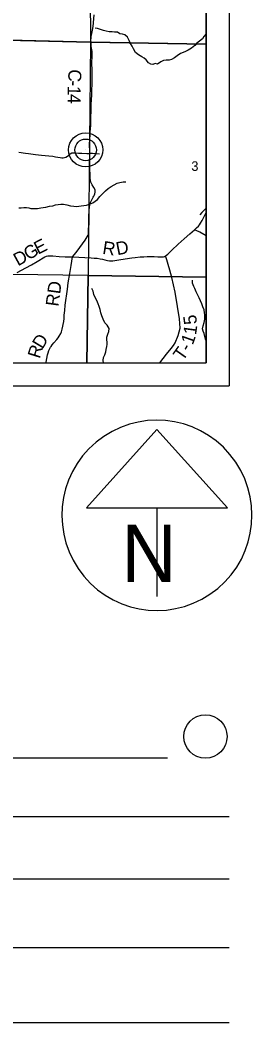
# Model space of a CAD drawing. Extents: x 0 to 34, y 0 to 22.
# Drawn here: x 8.087 to 9.099, y 11.222 to 15.595 of the extents above; entities that cross this region are included whole.
import ezdxf

# ---------------------------------------------------------------- set-up
doc = ezdxf.new("R2010")
doc.units = 0
for name, color, linetype in [('GM_X_Corporation', 7, 'Continuous'), ('GM_X_County_Road', 7, 'Continuous'), ('GM_X_County_Road_Text', 7, 'Continuous'), ('GM_X_Minor_River', 7, 'Continuous'), ('GM_X_Section_Text', 7, 'Continuous'), ('GM_X_Township_Road', 7, 'Continuous'), ('GM_X_Township_Road_Text', 7, 'Continuous'), ('GM_X_Unincorporated', 7, 'Continuous'), ('GM_X_Unincorporated_Location', 7, 'Continuous'), ('SH_Data', 7, 'Continuous'), ('TX_P_1', 7, 'Continuous')]:
    doc.layers.add(name, color=color, linetype=linetype)

msp = doc.modelspace()

# ---------------------------------------------------------------- linework, layer by layer
at = {"layer": 'GM_X_Corporation'}
for points in [[(2.1, 14.1), (8.9, 14.1), (8.9, 19.5152), (8.4033, 19.5268), (7.9795, 19.5354)], [(7.5629, 15.5187), (8.3936, 15.4979), (8.397, 15.4978), (8.9, 15.4893), (8.9, 19.5152), (8.4033, 19.5268), (7.9795, 19.5354)], [(4.3124, 14.1), (8.9, 14.1), (8.9, 15.4893), (8.397, 15.4978), (8.3936, 15.4979), (7.5629, 15.5187)]]:
    msp.add_lwpolyline(points, dxfattribs=at)
for points in [[(8.3875, 16.5502), (8.3939, 15.4987), (7.4137, 15.5211), (7.3478, 15.5216), (7.3577, 16.5425)], [(8.9, 15.489), (8.9, 16.5379), (8.3875, 16.5502), (8.3939, 15.4987)], [(7.4137, 15.5211), (8.3939, 15.4987), (8.3851, 14.4804), (7.3933, 14.4947)], [(8.9, 14.4732), (8.9, 15.489), (8.3939, 15.4987), (8.3851, 14.4804)], [(7.3859, 14.1), (8.378, 14.1), (8.3851, 14.4804), (7.3933, 14.4947)], [(8.378, 14.1), (8.9, 14.1), (8.9, 14.4732), (8.3851, 14.4804)]]:
    msp.add_lwpolyline(points, close=True, dxfattribs=at)
at = {"layer": 'GM_X_County_Road'}
for points in [[(8.3976, 15.4893), (8.3972, 15.4973), (8.3964, 15.5076), (8.3968, 15.5153), (8.3973, 15.5232), (8.3998, 15.536), (8.4032, 15.5499), (8.4061, 15.5666), (8.4103, 15.6171)], [(8.3154, 14.5616), (8.3248, 14.5731), (8.3358, 14.5877), (8.3708, 14.6345), (8.3802, 14.649), (8.384, 14.657), (8.3854, 14.6622), (8.3864, 14.6695), (8.387, 14.7092), (8.3876, 14.7355), (8.3892, 14.7657), (8.3905, 14.779), (8.3916, 14.7872), (8.3931, 14.7936), (8.3948, 14.7996), (8.3973, 14.8055), (8.4068, 14.8223), (8.4097, 14.8272), (8.412, 14.8332), (8.4135, 14.8375), (8.4152, 14.8438), (8.415, 14.849), (8.4144, 14.8542), (8.4097, 14.864), (8.4023, 14.8763), (8.3962, 14.8883), (8.3943, 14.8955), (8.393, 14.9049), (8.3925, 14.9201), (8.3921, 14.9449), (8.3917, 14.9775), (8.3923, 15.0132), (8.3921, 15.0209), (8.3915, 15.0289), (8.3905, 15.0436), (8.3906, 15.0562), (8.391, 15.0704), (8.3926, 15.0976), (8.3933, 15.1073), (8.3943, 15.1206), (8.3956, 15.1359), (8.3962, 15.1579), (8.3963, 15.1768), (8.3971, 15.1932), (8.3982, 15.225), (8.3997, 15.2477), (8.4003, 15.2673), (8.4011, 15.2881), (8.4012, 15.3167), (8.4014, 15.345), (8.4015, 15.3779), (8.4011, 15.4048), (8.4022, 15.4395), (8.4017, 15.4523), (8.4015, 15.4581), (8.4004, 15.4644), (8.3992, 15.4715), (8.3979, 15.4814), (8.3976, 15.4893)], [(8.0816, 15.0184), (8.1111, 15.0145), (8.124, 15.0128), (8.1549, 15.0085), (8.1808, 15.0056), (8.2128, 15.0029), (8.2305, 15.0006), (8.2421, 14.9988), (8.2629, 14.995), (8.2692, 14.9941), (8.2748, 14.9942), (8.2871, 14.997), (8.2941, 15.0018), (8.2997, 15.0061), (8.3057, 15.0112), (8.3136, 15.015), (8.3211, 15.0157), (8.3301, 15.0156), (8.3416, 15.0146), (8.3571, 15.0138), (8.3784, 15.0131), (8.3923, 15.0132)], [(8.3923, 15.0132), (8.3967, 15.0145), (8.4002, 15.0149), (8.4038, 15.0143), (8.4338, 15.0114)], [(8.3154, 14.5616), (8.3982, 14.5575), (8.4111, 14.5567), (8.4236, 14.5559), (8.4368, 14.5542), (8.4473, 14.5516), (8.4569, 14.5491), (8.4693, 14.5459), (8.4775, 14.5449), (8.4845, 14.5448), (8.4923, 14.5453), (8.5188, 14.5493), (8.5457, 14.5535), (8.5747, 14.5576), (8.5901, 14.5598), (8.611, 14.5617), (8.6273, 14.5628), (8.6424, 14.5634), (8.6732, 14.5634), (8.689, 14.563), (8.7049, 14.5624), (8.7139, 14.563), (8.7179, 14.5642), (8.7217, 14.5665), (8.727, 14.5701), (8.732, 14.5743), (8.7496, 14.5908), (8.777, 14.6172), (8.8031, 14.6412), (8.8282, 14.6622), (8.8488, 14.6804), (8.8579, 14.6885), (8.8655, 14.6967), (8.8699, 14.7021), (8.8754, 14.7094), (8.8825, 14.7214), (8.8882, 14.7324), (8.8955, 14.7472), (8.9, 14.7554)], [(8.0747, 14.4946), (8.1118, 14.5146), (8.1376, 14.528), (8.1622, 14.5422), (8.1956, 14.5621), (8.2019, 14.5645), (8.2078, 14.566), (8.2119, 14.5666), (8.2162, 14.5666), (8.2231, 14.5666), (8.2296, 14.566), (8.2582, 14.5642), (8.2836, 14.5628), (8.3154, 14.5616)], [(8.1998, 14.1), (8.2009, 14.1036), (8.2076, 14.1348), (8.2098, 14.1436), (8.2132, 14.1542), (8.2173, 14.1628), (8.2201, 14.168), (8.2232, 14.172), (8.2276, 14.178), (8.2353, 14.1873), (8.2475, 14.2016), (8.253, 14.2087), (8.2584, 14.2171), (8.2646, 14.2274), (8.2678, 14.2348), (8.2713, 14.2469), (8.2775, 14.2803), (8.2793, 14.2932), (8.2801, 14.3075), (8.2823, 14.3283), (8.2846, 14.3509), (8.294, 14.4212), (8.2976, 14.449), (8.3045, 14.4901), (8.3098, 14.5239), (8.3154, 14.5616)]]:
    msp.add_lwpolyline(points, dxfattribs=at)
at = {"layer": 'GM_X_Minor_River'}
for points in [[(8.9, 15.5347), (8.8888, 15.5226), (8.8828, 15.5124), (8.8703, 15.5032), (8.8594, 15.4937), (8.8503, 15.4835), (8.8348, 15.4724), (8.8216, 15.4633), (8.8087, 15.4579), (8.7985, 15.4537), (8.7872, 15.4484), (8.7732, 15.4381), (8.7619, 15.4301), (8.7479, 15.4225), (8.738, 15.419), (8.7244, 15.419), (8.7131, 15.4182), (8.7017, 15.4124), (8.6874, 15.4029), (8.6771, 15.4048), (8.6669, 15.401), (8.6574, 15.4028), (8.648, 15.4085), (8.6381, 15.4213), (8.6286, 15.4277), (8.618, 15.4341), (8.6047, 15.4436), (8.5903, 15.4538), (8.5819, 15.4685), (8.5758, 15.4806), (8.5697, 15.4924), (8.5636, 15.506), (8.5564, 15.5204), (8.5446, 15.5306), (8.5348, 15.5328), (8.523, 15.535), (8.5124, 15.5411), (8.4995, 15.5422), (8.4897, 15.5429), (8.4768, 15.5428), (8.4632, 15.5458), (8.4518, 15.5496), (8.4378, 15.5529), (8.4249, 15.5574), (8.4154, 15.5593)], [(8.0812, 14.7756), (8.0914, 14.7753), (8.1043, 14.7772), (8.1156, 14.7769), (8.1251, 14.7754), (8.1349, 14.7735), (8.1478, 14.7728), (8.1626, 14.7732), (8.1773, 14.7752), (8.1883, 14.7771), (8.1993, 14.7787), (8.2159, 14.7825), (8.2296, 14.7849), (8.2413, 14.7894), (8.2534, 14.7906), (8.2647, 14.7926), (8.2765, 14.7922), (8.292, 14.7889), (8.3076, 14.7847), (8.3216, 14.7829), (8.3337, 14.7822), (8.3443, 14.7834), (8.3541, 14.7853), (8.3655, 14.7865), (8.3765, 14.7876), (8.3905, 14.7919), (8.4044, 14.7984), (8.415, 14.8052), (8.4248, 14.8117), (8.4358, 14.8254), (8.4505, 14.8395), (8.4596, 14.8497), (8.472, 14.8596), (8.4853, 14.8684), (8.4981, 14.8764), (8.5106, 14.8833), (8.5231, 14.8864), (8.5378, 14.8891), (8.5488, 14.8887)], [(8.9, 14.775), (8.8926, 14.7678), (8.8805, 14.7556), (8.8715, 14.745)], [(8.8929, 14.29), (8.8933, 14.2995), (8.8929, 14.3089), (8.8921, 14.3188), (8.8905, 14.3313), (8.8852, 14.3438), (8.8802, 14.3578), (8.8753, 14.3711), (8.8695, 14.384), (8.8627, 14.3953), (8.8551, 14.4101), (8.8505, 14.4237), (8.8455, 14.4336), (8.8394, 14.448), (8.8398, 14.4609)], [(8.4323, 14.346), (8.4274, 14.3574), (8.422, 14.3714), (8.4156, 14.385), (8.4098, 14.3987), (8.4056, 14.4119), (8.4007, 14.4241)], [(8.4509, 14.1), (8.4501, 14.1098), (8.452, 14.1234), (8.4572, 14.1356), (8.4617, 14.1474), (8.4632, 14.158), (8.4658, 14.1709), (8.4677, 14.1804), (8.468, 14.1903), (8.4661, 14.2001), (8.4657, 14.2119), (8.4706, 14.2252), (8.4751, 14.2373), (8.4758, 14.2498), (8.4671, 14.2638), (8.4576, 14.2744), (8.4499, 14.2907), (8.4442, 14.3047), (8.4396, 14.318), (8.4373, 14.332), (8.4323, 14.346)], [(8.9, 14.1956), (8.8966, 14.2031), (8.8943, 14.2149), (8.8901, 14.2285), (8.8859, 14.2384), (8.884, 14.249), (8.8866, 14.2619), (8.8903, 14.2767), (8.8929, 14.29)]]:
    msp.add_lwpolyline(points, dxfattribs=at)
at = {"layer": 'GM_X_Township_Road'}
for points in [[(8.8488, 14.6804), (8.8537, 14.678), (8.8595, 14.6753), (8.8713, 14.6706), (8.9, 14.6552)], [(8.6976, 14.1), (8.7022, 14.1057), (8.7124, 14.1194), (8.7265, 14.1374), (8.7469, 14.1624), (8.7567, 14.1761), (8.764, 14.1867), (8.7769, 14.2196), (8.7861, 14.252), (8.7832, 14.2916), (8.7738, 14.3451), (8.7641, 14.4088), (8.7503, 14.4724), (8.7414, 14.5047), (8.7339, 14.529), (8.7282, 14.5494), (8.7217, 14.5665)]]:
    msp.add_lwpolyline(points, dxfattribs=at)
at = {"layer": 'GM_X_Unincorporated'}
for radius in [0.0744, 0.0472]:
    msp.add_circle((8.3736, 15.0285), radius, dxfattribs=at)
at = {"layer": 'GM_X_Unincorporated_Location'}
msp.add_line((8.3736, 15.0285), (8.3736, 15.0285), dxfattribs=at)
at = {"layer": 'SH_Data'}
for p, q in [((9, 21), (9, 14)), ((8.9, 20.9), (8.9, 14.1)), ((2.1, 14.1), (8.9, 14.1)), ((2, 14), (9, 14)), ((8.6845, 13.8091), (8.3769, 13.4678)), ((8.9921, 13.4678), (8.6845, 13.8091)), ((8.3769, 13.4678), (8.9921, 13.4678)), ((8.6845, 13.4678), (8.6845, 13.0811)), ((8.6845, 13.4353), (8.6845, 13.4353)), ((8.6845, 13.4353), (8.6845, 13.4353)), ((8.7306, 12.3767), (4.4937, 12.3767)), ((9, 12.1207), (7.75, 12.1207)), ((9, 11.8491), (7.75, 11.8491)), ((9, 11.5491), (7.75, 11.5491)), ((9, 11.2223), (7.75, 11.2223))]:
    msp.add_line(p, q, dxfattribs=at)
msp.add_arc((8.6845, 13.4353), 0.4148, 129.7798, 129.7633, dxfattribs=at)
at = {"layer": 'TX_P_1'}
msp.add_circle((8.8961, 12.4712), 0.0945, dxfattribs=at)

# ---------------------------------------------------------------- texts
at = {"layer": 'GM_X_County_Road_Text'}
for s, height, rotation, p in [('C', 0.0568, 265.4717, (8.3001, 15.3817)), ('-', 0.0568, 267.9834, (8.2962, 15.3325)), ('1', 0.0568, 269.0142, (8.2954, 15.3081)), ('4', 0.0568, 269.8612, (8.2948, 15.2721)), ('G', 0.0568, 31.0693, (8.1239, 14.5457)), ('E', 0.0568, 27.1745, (8.1658, 14.571)), ('R', 0.0568, 351.0927, (8.4443, 14.5758)), ('D', 0.0568, 10.9525, (8.5115, 14.569)), ('D', 0.0568, 28.7869, (8.0779, 14.5204)), ('RD', 0.05682, 82.2794, (8.2546, 14.3437)), ('D', 0.0568, 59.0075, (8.1852, 14.1572)), ('R', 0.0568, 72.8168, (8.1729, 14.1159))]:
    msp.add_text(s, height=height, rotation=rotation, dxfattribs=at).set_placement(p)
at = {"layer": 'GM_X_Section_Text'}
msp.add_text('3', height=0.0419, rotation=0, dxfattribs=at).set_placement((8.8346, 14.9368))
at = {"layer": 'GM_X_Township_Road_Text'}
for s, rotation, p in [('5', 97.2037, (8.8601, 14.2706)), ('1', 82.1553, (8.8553, 14.22)), ('1', 70.5614, (8.8408, 14.1751)), ('T', 54.8486, (8.7974, 14.1051)), ('-', 61.082, (8.8254, 14.1455))]:
    msp.add_text(s, height=0.0568, rotation=rotation, dxfattribs=at).set_placement(p)
at = {"layer": 'SH_Data'}
msp.add_text('N', height=0.25, dxfattribs=at).set_placement((8.5292, 13.144))

doc.saveas('drawing.dxf')
